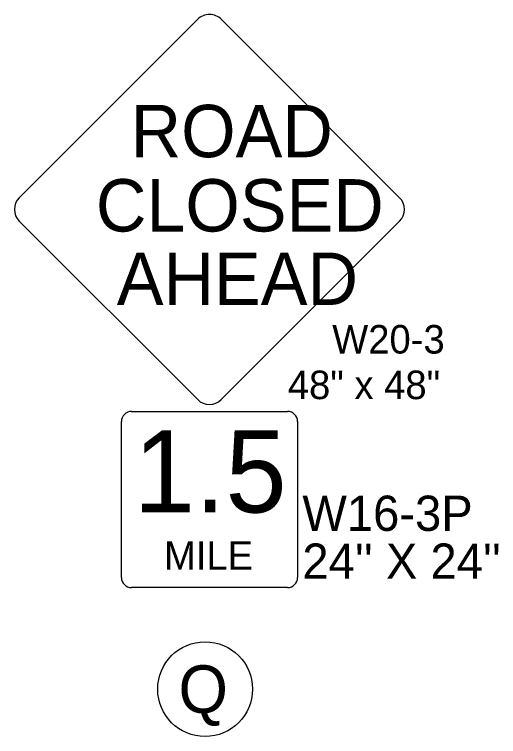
# Model space of a CAD drawing. Extents: x 2157572 to 5059327, y 715220 to 1674494.
# Drawn here: x 2168205 to 2168700, y 729302 to 730040 of the extents above; entities that cross this region are included whole.
import ezdxf

# ---------------------------------------------------------------- set-up
doc = ezdxf.new("R2010")
doc.units = 0
for name, color, linetype in [('Exist Cultural Church Label', 7, 'Continuous'), ('Exist Hydrographic Creek Single Shore Label', 7, 'Continuous'), ('Exist Road Secondary Type 20 SR Number Label', 7, 'Continuous'), ('Map Preparation County Base KeyMap CELL', 7, 'Continuous'), ('Map Preparation County Base Legend Highway Garage or Maintenance Office', 7, 'Continuous')]:
    doc.layers.add(name, color=color, linetype=linetype)

msp = doc.modelspace()

# ---------------------------------------------------------------- linework, layer by layer
at = {"layer": 'Exist Cultural Church Label'}
msp.add_circle((2168399.88, 729350.57), 48.43, dxfattribs=at)
at = {"layer": 'Exist Hydrographic Creek Single Shore Label'}
for points in [[(2168324.77, 729634.43), (2168404.33, 729634.43)], [(2168404.33, 729634.43), (2168483.88, 729634.43)], [(2168314.27, 729464.82), (2168314.27, 729623.93)], [(2168494.38, 729623.93), (2168494.38, 729464.82)], [(2168404.33, 729454.32), (2168324.77, 729454.32)], [(2168483.88, 729454.32), (2168404.33, 729454.32)]]:
    msp.add_lwpolyline(points, dxfattribs=at)
for centre, start, end in [((2168324.78, 729623.93), 89.98697, 180), ((2168483.88, 729623.93), 360, 90), ((2168324.78, 729464.83), 180, 270), ((2168483.88, 729464.83), 270, 360)]:
    msp.add_arc(centre, 10.51, start, end, dxfattribs=at)
at = {"layer": 'Exist Road Secondary Type 20 SR Number Label'}
for points in [[(2168210.03, 729852.8), (2168392.29, 730035.06)], [(2168416.37, 730035.06), (2168598.62, 729852.8)], [(2168392.29, 729646.47), (2168210.03, 729828.73)], [(2168598.62, 729828.73), (2168416.37, 729646.47)]]:
    msp.add_lwpolyline(points, dxfattribs=at)
for centre, start, end in [((2168404.33, 730023.02), 44.98697, 135), ((2168222.06, 729840.76), 135, 225), ((2168586.58, 729840.76), 315, 45), ((2168404.33, 729658.5), 225, 315)]:
    msp.add_arc(centre, 17.02, start, end, dxfattribs=at)
at = {"layer": 'Map Preparation County Base Legend Highway Garage or Maintenance Office'}
msp.add_circle((2168399.88, 729350.57), 48.43, dxfattribs=at)

# ---------------------------------------------------------------- texts
at = {"layer": 'Exist Cultural Church Label'}
msp.add_text('Q', height=48.63, dxfattribs=at).set_placement((2168372.64, 729326.26))
at = {"layer": 'Exist Road Secondary Type 20 SR Number Label'}
for s, height, p in [('ROAD', 53.496, (2168323.7, 729894.16)), ('CLOSED', 53.496, (2168288.23, 729818.23)), ('AHEAD', 53.496, (2168309.64, 729743.22)), ('W20-3', 29.18, (2168529.71, 729693.51)), ('48" x 48"', 29.18, (2168484.33, 729646.94))]:
    msp.add_text(s, height=height, dxfattribs=at).set_placement(p)
at = {"layer": 'Map Preparation County Base KeyMap CELL'}
for s, height, p in [('1.5', 84.055, (2168326.92, 729531.15)), ('W16-3P', 36.024, (2168499.24, 729512.3)), ('MILE', 29.179, (2168357.84, 729472.57)), ("24'' X 24''", 36.0236, (2168499.24, 729463.37))]:
    msp.add_text(s, height=height, rotation=360, dxfattribs=at).set_placement(p)

doc.saveas('drawing.dxf')
